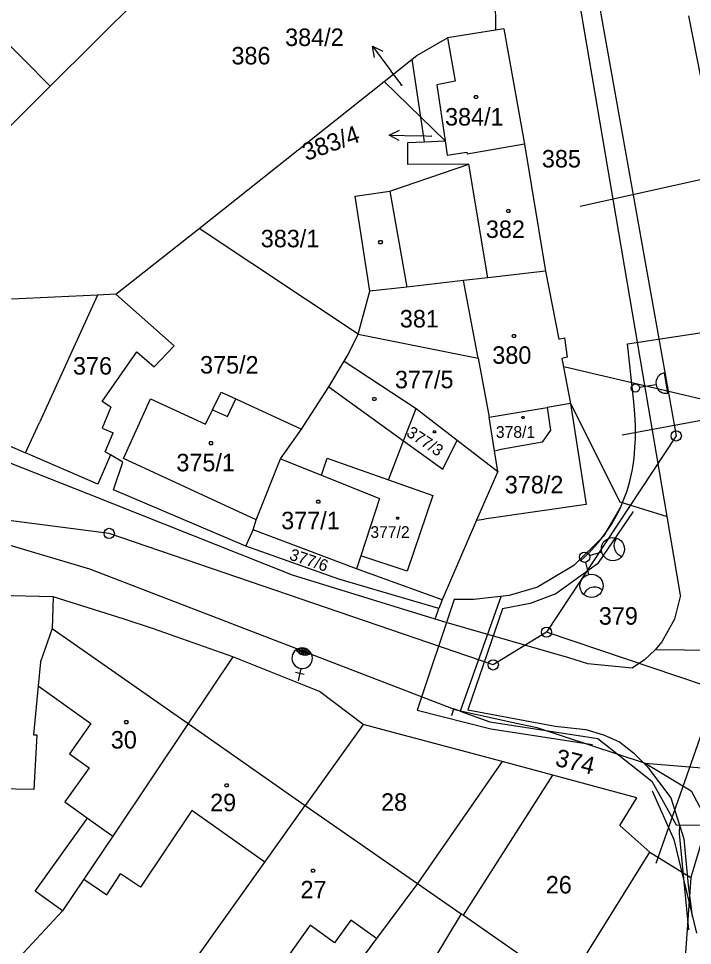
# Model space of a CAD drawing. Extents: x -639621 to -639329, y -1192893 to -1192488.
# Drawn here: x -639562.8 to -639497.3, y -1192743.8 to -1192653.7 of the extents above; entities that cross this region are included whole.
import ezdxf

# ---------------------------------------------------------------- set-up
doc = ezdxf.new("R2010")
doc.units = 0
for name, color, linetype in [('Vrstva 1', 7, 'Continuous'), ('Vrstva 19', 7, 'Continuous'), ('Vrstva 2', 7, 'Continuous'), ('Vrstva 20', 7, 'Continuous'), ('Vrstva 21', 7, 'Continuous'), ('Vrstva 22', 7, 'Continuous'), ('Vrstva 24', 7, 'Continuous'), ('Vrstva 25', 7, 'Continuous'), ('Vrstva 4', 7, 'Continuous'), ('Vrstva 5', 7, 'Continuous'), ('Vrstva 7', 7, 'Continuous')]:
    doc.layers.add(name, color=color, linetype=linetype)

msp = doc.modelspace()

# ---------------------------------------------------------------- linework, layer by layer
at = {"layer": 'Vrstva 1'}
for p, q in [((-639516.92, -1192617.59), (-639516.39, -1192654.83)), ((-639499.71, -1192702.08), (-639511.27, -1192634.08)), ((-639559.67, -1192660.27), (-639546.32, -1192646.99)), ((-639568.41, -1192651.47), (-639559.67, -1192660.27)), ((-639490.92, -1192687.58), (-639497.61, -1192653.45)), ((-639516.39, -1192654.83), (-639521.06, -1192655.58)), ((-639515.58, -1192654.7), (-639516.39, -1192654.83)), ((-639515.58, -1192654.7), (-639513.58, -1192665.9)), ((-639524.03, -1192657.28), (-639521.06, -1192655.58)), ((-639527.23, -1192659.81), (-639524.51, -1192657.66)), ((-639524.51, -1192657.66), (-639524.03, -1192657.28)), ((-639523.66, -1192663.29), (-639524.51, -1192657.66)), ((-639573.4, -1192673.94), (-639559.67, -1192660.27)), ((-639545.2, -1192674.09), (-639527.23, -1192659.81)), ((-639523.66, -1192663.29), (-639527.23, -1192659.81)), ((-639523.66, -1192663.29), (-639521.3, -1192665.59)), ((-639523.3, -1192665.67), (-639523.66, -1192663.29)), ((-639524.92, -1192665.73), (-639523.3, -1192665.67)), ((-639524.91, -1192667.89), (-639524.92, -1192665.73)), ((-639523.3, -1192665.67), (-639521.3, -1192665.59)), ((-639521.3, -1192665.59), (-639521.09, -1192666.98)), ((-639513.58, -1192665.9), (-639519.15, -1192666.89)), ((-639513.58, -1192665.9), (-639511.54, -1192678.25)), ((-639521.09, -1192666.98), (-639519.18, -1192666.7)), ((-639519.18, -1192666.7), (-639519.15, -1192666.89)), ((-639526.67, -1192670.46), (-639518.99, -1192667.84)), ((-639518.99, -1192667.84), (-639524.91, -1192667.89)), ((-639530.04, -1192670.97), (-639526.67, -1192670.46)), ((-639528.62, -1192680.2), (-639530.04, -1192670.97)), ((-639553.28, -1192680.5), (-639545.2, -1192674.09)), ((-639529.75, -1192684.37), (-639545.2, -1192674.09)), ((-639511.54, -1192678.25), (-639517.13, -1192678.89)), ((-639511.54, -1192678.25), (-639510.25, -1192684.87)), ((-639519.5, -1192679.16), (-639525, -1192679.79)), ((-639517.13, -1192678.89), (-639519.5, -1192679.16)), ((-639518.08, -1192686.72), (-639519.5, -1192679.16)), ((-639529.75, -1192684.37), (-639528.62, -1192680.2)), ((-639525, -1192679.79), (-639528.62, -1192680.2)), ((-639555.06, -1192680.58), (-639563.42, -1192680.98)), ((-639555.06, -1192680.58), (-639560.72, -1192692.94)), ((-639553.28, -1192680.5), (-639555.06, -1192680.58)), ((-639547.62, -1192685.52), (-639553.28, -1192680.5)), ((-639530.73, -1192686.34), (-639529.75, -1192684.37)), ((-639529.75, -1192684.37), (-639518.08, -1192686.72)), ((-639510.25, -1192684.87), (-639509.7, -1192684.74)), ((-639509.7, -1192684.74), (-639509.43, -1192686.62)), ((-639549.57, -1192687.53), (-639547.62, -1192685.52)), ((-639554.62, -1192690.9), (-639551.25, -1192686.09)), ((-639551.25, -1192686.09), (-639549.57, -1192687.53)), ((-639531.11, -1192686.99), (-639530.73, -1192686.34)), ((-639509.43, -1192686.62), (-639509.96, -1192686.74)), ((-639532.58, -1192689.5), (-639531.11, -1192686.99)), ((-639531.11, -1192686.99), (-639524.12, -1192691.61)), ((-639518.08, -1192686.72), (-639517.01, -1192692.43)), ((-639509.96, -1192686.74), (-639509.12, -1192691.12)), ((-639543.9, -1192691.72), (-639543.06, -1192690)), ((-639543.06, -1192690), (-639541.63, -1192690.66)), ((-639535.25, -1192693.61), (-639532.58, -1192689.5)), ((-639553.78, -1192691.45), (-639554.62, -1192690.9)), ((-639552.55, -1192696.45), (-639549.92, -1192690.66)), ((-639549.92, -1192690.66), (-639544.58, -1192693.13)), ((-639541.63, -1192690.66), (-639535.25, -1192693.61)), ((-639509.12, -1192691.12), (-639511.39, -1192691.5)), ((-639509.12, -1192691.12), (-639504.3, -1192700.68)), ((-639509.12, -1192691.12), (-639507.59, -1192700.94)), ((-639553.78, -1192691.45), (-639554.63, -1192693.5)), ((-639544.58, -1192693.13), (-639543.9, -1192691.72)), ((-639525.33, -1192694.73), (-639524.12, -1192691.61)), ((-639524.12, -1192691.61), (-639520.13, -1192694.67)), ((-639517.01, -1192692.43), (-639511.39, -1192691.5)), ((-639511.39, -1192691.5), (-639511.04, -1192693.7)), ((-639562.08, -1192695.91), (-639560.72, -1192692.94)), ((-639516.49, -1192695.7), (-639517.01, -1192692.43)), ((-639554.63, -1192693.5), (-639553.55, -1192693.95)), ((-639537.29, -1192696.49), (-639535.25, -1192693.61)), ((-639511.04, -1192693.7), (-639511.86, -1192694.86)), ((-639564.69, -1192694.76), (-639562.08, -1192695.91)), ((-639554.32, -1192695.81), (-639553.55, -1192693.95)), ((-639526.8, -1192698.52), (-639525.33, -1192694.73)), ((-639520.13, -1192694.67), (-639516.17, -1192697.71)), ((-639516.49, -1192695.7), (-639516.03, -1192695.62)), ((-639511.86, -1192694.86), (-639516.03, -1192695.62)), ((-639556.03, -1192699.88), (-639564.99, -1192696.36)), ((-639555.03, -1192698.94), (-639562.08, -1192695.91)), ((-639553.81, -1192696.1), (-639555.03, -1192698.94)), ((-639553.81, -1192696.1), (-639554.32, -1192695.81)), ((-639552.6, -1192696.8), (-639553.81, -1192696.1)), ((-639539.66, -1192702.42), (-639552.55, -1192696.45)), ((-639539.66, -1192702.42), (-639537.29, -1192696.49)), ((-639533.3, -1192698.08), (-639532.75, -1192696.42)), ((-639532.75, -1192696.42), (-639526.8, -1192698.52)), ((-639516.17, -1192697.71), (-639516.49, -1192695.7)), ((-639553.52, -1192699.51), (-639552.6, -1192696.8)), ((-639533.3, -1192698.08), (-639527.66, -1192700.33)), ((-639516.17, -1192697.71), (-639518.23, -1192702.46)), ((-639526.8, -1192698.52), (-639522.5, -1192700.06)), ((-639536.13, -1192707.8), (-639556.03, -1192699.88)), ((-639540.65, -1192704.97), (-639553.52, -1192699.51)), ((-639522.5, -1192700.06), (-639524.99, -1192707.41)), ((-639527.66, -1192700.33), (-639529.47, -1192705.92)), ((-639507.59, -1192700.94), (-639517.51, -1192702.36)), ((-639504.3, -1192700.68), (-639499.71, -1192702.08)), ((-639539.95, -1192703.37), (-639539.66, -1192702.42)), ((-639518.23, -1192702.46), (-639521.59, -1192710.19)), ((-639518.23, -1192702.46), (-639517.51, -1192702.36)), ((-639498.41, -1192709.74), (-639499.71, -1192702.08)), ((-639567.36, -1192703.76), (-639555.84, -1192707.16)), ((-639540.65, -1192704.97), (-639539.95, -1192703.37)), ((-639529.9, -1192707.18), (-639539.95, -1192703.37)), ((-639531.62, -1192708.19), (-639540.65, -1192704.97)), ((-639529.47, -1192705.92), (-639529.9, -1192707.18)), ((-639524.99, -1192707.41), (-639529.47, -1192705.92)), ((-639555.84, -1192707.16), (-639520.25, -1192720.87)), ((-639521.59, -1192710.19), (-639529.9, -1192707.18)), ((-639522.25, -1192712.07), (-639536.13, -1192707.8)), ((-639521.89, -1192711.04), (-639531.62, -1192708.19)), ((-639559.39, -1192709.9), (-639575.47, -1192709.49)), ((-639559.39, -1192709.9), (-639559.48, -1192712.99)), ((-639552.59, -1192712.04), (-639559.39, -1192709.9)), ((-639498.41, -1192709.74), (-639499.01, -1192712.06)), ((-639521.59, -1192710.19), (-639521.89, -1192711.04)), ((-639522.25, -1192712.07), (-639521.89, -1192711.04)), ((-639549.63, -1192713), (-639552.59, -1192712.04)), ((-639521.18, -1192712.4), (-639522.25, -1192712.07)), ((-639509.27, -1192715.82), (-639521.18, -1192712.4)), ((-639499.01, -1192712.06), (-639500.24, -1192714.27)), ((-639559.48, -1192712.99), (-639560.6, -1192716.22)), ((-639541.91, -1192715.74), (-639549.63, -1192713)), ((-639500.24, -1192714.27), (-639500.89, -1192715.05)), ((-639500.89, -1192715.05), (-639501.93, -1192716.01)), ((-639485.5, -1192715.26), (-639500.89, -1192715.05)), ((-639560.6, -1192716.22), (-639560.83, -1192718.54)), ((-639541.91, -1192715.74), (-639546.26, -1192722.22)), ((-639533.5, -1192719.11), (-639541.91, -1192715.74)), ((-639507.41, -1192716.4), (-639509.27, -1192715.82)), ((-639503.12, -1192716.84), (-639507.41, -1192716.4)), ((-639501.93, -1192716.01), (-639503.12, -1192716.84)), ((-639560.83, -1192718.54), (-639561.29, -1192723.32)), ((-639560.83, -1192718.54), (-639555.71, -1192722.22)), ((-639529.26, -1192722.31), (-639533.5, -1192719.11)), ((-639520.25, -1192720.87), (-639514.8, -1192722.07)), ((-639555.71, -1192722.22), (-639557.8, -1192725.14)), ((-639546.26, -1192722.22), (-639553.6, -1192733.16)), ((-639529.26, -1192722.31), (-639534.88, -1192730.18)), ((-639515.75, -1192725.9), (-639529.26, -1192722.31)), ((-639514.8, -1192722.07), (-639512.37, -1192722.6)), ((-639512.37, -1192722.6), (-639501.84, -1192726.06)), ((-639561.29, -1192723.32), (-639560.98, -1192723.31)), ((-639560.98, -1192723.31), (-639561.27, -1192728.63)), ((-639557.8, -1192725.14), (-639555.88, -1192726.52)), ((-639515.75, -1192725.9), (-639523.97, -1192737.75)), ((-639510.81, -1192727.24), (-639515.75, -1192725.9)), ((-639501.84, -1192726.06), (-639484.21, -1192727.56)), ((-639501.84, -1192726.06), (-639497.38, -1192728.76)), ((-639555.88, -1192726.52), (-639558.25, -1192729.81)), ((-639519.51, -1192740.84), (-639510.81, -1192727.24)), ((-639502.67, -1192729.44), (-639510.81, -1192727.24)), ((-639561.27, -1192728.63), (-639565.56, -1192728.52)), ((-639497.38, -1192728.76), (-639495.79, -1192731.74)), ((-639558.25, -1192729.81), (-639556.04, -1192731.4)), ((-639504.3, -1192732.11), (-639502.67, -1192729.44)), ((-639538.8, -1192735.67), (-639534.88, -1192730.18)), ((-639534.88, -1192730.18), (-639523.97, -1192737.75)), ((-639561.14, -1192738.49), (-639556.04, -1192731.4)), ((-639501.41, -1192734.7), (-639504.3, -1192732.11)), ((-639495.79, -1192731.74), (-639497.4, -1192737.18)), ((-639553.6, -1192733.16), (-639556.41, -1192737.34)), ((-639509.52, -1192747.76), (-639501.41, -1192734.7)), ((-639501.41, -1192734.7), (-639497.4, -1192737.18)), ((-639551.56, -1192753.52), (-639538.8, -1192735.67)), ((-639556.41, -1192737.34), (-639558.48, -1192740.42)), ((-639523.97, -1192737.75), (-639527.96, -1192743.09)), ((-639497.4, -1192737.18), (-639499.22, -1192762.27)), ((-639558.48, -1192740.42), (-639561.14, -1192738.49)), ((-639558.48, -1192740.42), (-639567.88, -1192750.5)), ((-639519.72, -1192740.7), (-639522.79, -1192745.74)), ((-639519.72, -1192740.7), (-639519.51, -1192740.84)), ((-639519.51, -1192740.84), (-639509.52, -1192747.76)), ((-639527.96, -1192743.09), (-639541.39, -1192761.03))]:
    msp.add_line(p, q, dxfattribs=at)
at = {"layer": 'Vrstva 19'}
for points in [[(-639583.962, -1192528.01), (-639550.452, -1192564.184), (-639529.583, -1192588.026), (-639514.491, -1192612.048), (-639507.737, -1192644.326), (-639498.832, -1192694.254), (-639511.439, -1192713.331), (-639516.613, -1192716.507), (-639553.938, -1192703.739), (-639570.485, -1192701.616), (-639578.687, -1192703.18)], [(-639355.755, -1192712.633), (-639405.298, -1192719.503), (-639444.905, -1192722.803), (-639490.998, -1192720.223), (-639511.439, -1192713.331)]]:
    msp.add_lwpolyline(points, dxfattribs=at)
for centre in [(-639498.832, -1192694.254), (-639553.938, -1192703.739), (-639511.439, -1192713.331), (-639516.613, -1192716.507)]:
    msp.add_circle(centre, 0.5, dxfattribs=at)
at = {"layer": 'Vrstva 20'}
for points in [[(-639509.769, -1192687.519), (-639485.819, -1192693.156)], [(-639500.783, -1192735.773), (-639485.819, -1192693.156)]]:
    msp.add_lwpolyline(points, dxfattribs=at)
at = {"layer": 'Vrstva 21'}
msp.add_lwpolyline([(-639504.241, -1192701.192), (-639505.905, -1192703.987), (-639508.782, -1192706.864), (-639512.31, -1192708.965), (-639515.077, -1192709.767), (-639518.505, -1192710.144), (-639520.398, -1192710.144), (-639524.02, -1192720.907), (-639516.84, -1192722.729), (-639509.886, -1192723.806), (-639506.984, -1192724.251)], dxfattribs=at)
at = {"layer": 'Vrstva 22'}
for p, q in [((-639502.402, -1192689.51), (-639500.799, -1192689.247)), ((-639507.267, -1192705.866), (-639506.075, -1192705.531)), ((-639507.66, -1192706.539), (-639507.366, -1192707.742)), ((-639535.778, -1192715.073), (-639534.348, -1192715.371)), ((-639535.662, -1192715.212), (-639535.613, -1192714.974)), ((-639534.489, -1192715.453), (-639535.643, -1192715.216)), ((-639535.613, -1192714.974), (-639534.441, -1192715.216)), ((-639535.409, -1192714.892), (-639535.504, -1192715.349)), ((-639535.504, -1192715.349), (-639534.66, -1192715.523)), ((-639534.567, -1192715.076), (-639535.409, -1192714.892)), ((-639535.199, -1192714.874), (-639535.297, -1192715.453)), ((-639535.297, -1192715.453), (-639534.855, -1192715.565)), ((-639534.734, -1192714.981), (-639535.18, -1192714.886)), ((-639534.98, -1192714.918), (-639535.105, -1192715.524)), ((-639534.855, -1192715.565), (-639534.734, -1192714.981)), ((-639534.66, -1192715.523), (-639534.567, -1192715.076)), ((-639534.441, -1192715.216), (-639534.489, -1192715.453)), ((-639535.831, -1192717.215), (-639535.001, -1192717.396)), ((-639535.3, -1192716.856), (-639535.56, -1192718.049))]:
    msp.add_line(p, q, dxfattribs=at)
for points in [[(-639503.007, -1192690.368), (-639503.57, -1192685.327), (-639487.98, -1192682.937)], [(-639499.645, -1192690.103), (-639499.969, -1192688.128)], [(-639508.109, -1192706.375), (-639507.734, -1192706.044), (-639507.157, -1192705.475), (-639506.662, -1192704.935), (-639506.183, -1192704.36), (-639505.628, -1192703.614), (-639505.097, -1192702.802), (-639504.638, -1192701.997), (-639504.261, -1192701.237), (-639503.907, -1192700.41), (-639503.612, -1192699.594), (-639503.33, -1192698.641), (-639503.082, -1192697.518), (-639502.921, -1192696.417), (-639502.841, -1192695.404), (-639502.805, -1192694.473), (-639502.803, -1192693.26), (-639502.846, -1192692.155), (-639502.942, -1192690.954), (-639503.007, -1192690.373)]]:
    msp.add_lwpolyline(points, dxfattribs=at)
for centre, radius in [((-639502.796, -1192689.602), 0.4), ((-639504.983, -1192705.259), 1.125), ((-639507.734, -1192706.044), 0.5), ((-639507.065, -1192708.826), 1.125)]:
    msp.add_circle(centre, radius, dxfattribs=at)
for centre, radius, start, end in [((-639499.807, -1192689.116), 1.001, 99.30226, 189.30226), ((-639499.807, -1192689.116), 1.001, 189.30226, 279.30226), ((-639503.755, -1192704.904), 1.125, 140.76439, 251.47672), ((-639506.771, -1192710.07), 1.125, 47.9657, 158.67804), ((-639535.182, -1192715.862), 1, 125.42147, 124.57372), ((-639534.909, -1192714.542), 1, 210.62549, 306.53322)]:
    msp.add_arc(centre, radius, start, end, dxfattribs=at)
at = {"layer": 'Vrstva 24'}
for p, q in [((-639520.47, -1192720.793), (-639520.657, -1192721.474)), ((-639519.839, -1192721.018), (-639520.47, -1192720.793)), ((-639498.498, -1192732.895), (-639498.489, -1192732.056)), ((-639497.601, -1192742.26), (-639498.498, -1192732.895))]:
    msp.add_line(p, q, dxfattribs=at)
msp.add_lwpolyline([(-639515.87, -1192709.897), (-639519.839, -1192721.018), (-639516.938, -1192722.054), (-639506.439, -1192723.649), (-639501.216, -1192727.825), (-639498.838, -1192732.052), (-639488.74, -1192732.165), (-639484.493, -1192728.011), (-639466.499, -1192728.212)], dxfattribs=at)
at = {"layer": 'Vrstva 25'}
for p, q in [((-639493.98, -1192668.81), (-639508.152, -1192671.961)), ((-639501.158, -1192728.756), (-639499.048, -1192733.476)), ((-639499.048, -1192733.476), (-639496.86, -1192742.59))]:
    msp.add_line(p, q, dxfattribs=at)
for points in [[(-639460.277, -1192719.081), (-639470.702, -1192714.682), (-639477.01, -1192709.489), (-639481.198, -1192702.482), (-639485.834, -1192697.846), (-639487.986, -1192691.193), (-639504.096, -1192694.186)], [(-639503.001, -1192701.594), (-639506.486, -1192706.69), (-639510.516, -1192709.592), (-639513.013, -1192710.551), (-639515.716, -1192711.06), (-639519.07, -1192720.886), (-639510.612, -1192722.45), (-639507.627, -1192722.785), (-639505.909, -1192723.303), (-639504.328, -1192723.976), (-639502.972, -1192725.053), (-639501.648, -1192726.377), (-639499.349, -1192729.422), (-639498.089, -1192733.403), (-639497.666, -1192737.93), (-639497.276, -1192740.949)]]:
    msp.add_lwpolyline(points, dxfattribs=at)
at = {"layer": 'Vrstva 4'}
for p, q in [((-639521.06, -1192655.58), (-639520.33, -1192659.8)), ((-639520.33, -1192659.8), (-639522.11, -1192660.14)), ((-639522.11, -1192660.14), (-639521.3, -1192665.59)), ((-639517.13, -1192678.89), (-639518.99, -1192667.84)), ((-639526.67, -1192670.46), (-639525, -1192679.79)), ((-639532.58, -1192689.5), (-639525.33, -1192694.73)), ((-639542.44, -1192692.36), (-639541.63, -1192690.66)), ((-639543.9, -1192691.72), (-639542.44, -1192692.36)), ((-639525.33, -1192694.73), (-639521.51, -1192697.49)), ((-639521.51, -1192697.49), (-639520.13, -1192694.67)), ((-639537.29, -1192696.49), (-639533.3, -1192698.08)), ((-639559.48, -1192712.99), (-639546.26, -1192722.22)), ((-639546.26, -1192722.22), (-639534.88, -1192730.18)), ((-639545.9, -1192730.65), (-639550.91, -1192738.12)), ((-639538.8, -1192735.67), (-639545.9, -1192730.65)), ((-639556.04, -1192731.4), (-639553.6, -1192733.16)), ((-639554.18, -1192738.84), (-639552.83, -1192736.83)), ((-639550.91, -1192738.12), (-639552.83, -1192736.83)), ((-639556.41, -1192737.34), (-639554.18, -1192738.84)), ((-639523.97, -1192737.75), (-639519.72, -1192740.7)), ((-639530.45, -1192741.31), (-639532.03, -1192743.51)), ((-639527.96, -1192743.09), (-639530.45, -1192741.31)), ((-639534.41, -1192741.81), (-639537.06, -1192745.52)), ((-639532.03, -1192743.51), (-639534.41, -1192741.81))]:
    msp.add_line(p, q, dxfattribs=at)
at = {"layer": 'Vrstva 5'}
for points in [[(-639518.19, -1192661.18), (-639518.1, -1192661.33), (-639518.19, -1192661.48), (-639518.37, -1192661.48), (-639518.46, -1192661.33), (-639518.37, -1192661.18)], [(-639515.07, -1192672.25), (-639514.98, -1192672.4), (-639515.07, -1192672.55), (-639515.25, -1192672.55), (-639515.34, -1192672.4), (-639515.25, -1192672.25)], [(-639527.48, -1192675.28), (-639527.39, -1192675.43), (-639527.48, -1192675.58), (-639527.66, -1192675.58), (-639527.75, -1192675.43), (-639527.66, -1192675.28)], [(-639514.52, -1192684.4), (-639514.43, -1192684.55), (-639514.52, -1192684.7), (-639514.7, -1192684.7), (-639514.79, -1192684.55), (-639514.7, -1192684.4)], [(-639528.07, -1192690.52), (-639527.98, -1192690.67), (-639528.07, -1192690.82), (-639528.25, -1192690.82), (-639528.34, -1192690.67), (-639528.25, -1192690.52)], [(-639513.67, -1192692.38), (-639513.609, -1192692.48), (-639513.67, -1192692.58), (-639513.79, -1192692.58), (-639513.851, -1192692.48), (-639513.79, -1192692.38)], [(-639522.27, -1192693.75), (-639522.209, -1192693.85), (-639522.27, -1192693.95), (-639522.39, -1192693.95), (-639522.451, -1192693.85), (-639522.39, -1192693.75)], [(-639543.96, -1192694.81), (-639543.87, -1192694.96), (-639543.96, -1192695.11), (-639544.14, -1192695.11), (-639544.23, -1192694.96), (-639544.14, -1192694.81)], [(-639533.53, -1192700.51), (-639533.44, -1192700.66), (-639533.53, -1192700.81), (-639533.71, -1192700.81), (-639533.8, -1192700.66), (-639533.71, -1192700.51)], [(-639525.84, -1192702.15), (-639525.779, -1192702.25), (-639525.84, -1192702.35), (-639525.96, -1192702.35), (-639526.021, -1192702.25), (-639525.96, -1192702.15)], [(-639552.19, -1192721.93), (-639552.1, -1192722.08), (-639552.19, -1192722.23), (-639552.37, -1192722.23), (-639552.46, -1192722.08), (-639552.37, -1192721.93)], [(-639542.44, -1192728.07), (-639542.35, -1192728.22), (-639542.44, -1192728.37), (-639542.62, -1192728.37), (-639542.71, -1192728.22), (-639542.62, -1192728.07)], [(-639534.03, -1192736.35), (-639533.94, -1192736.5), (-639534.03, -1192736.65), (-639534.21, -1192736.65), (-639534.3, -1192736.5), (-639534.21, -1192736.35)]]:
    msp.add_lwpolyline(points, close=True, dxfattribs=at)
at = {"layer": 'Vrstva 7'}
for p, q in [((-639528.361, -1192656.371), (-639526.56, -1192658.77)), ((-639525.47, -1192660.22), (-639526.56, -1192658.77)), ((-639526.729, -1192665.018), (-639523.73, -1192665.11)), ((-639522.57, -1192665.15), (-639523.73, -1192665.11))]:
    msp.add_line(p, q, dxfattribs=at)
for points in [[(-639528.161, -1192657.471), (-639528.361, -1192656.371), (-639527.361, -1192656.87)], [(-639525.744, -1192665.548), (-639526.729, -1192665.018), (-639525.714, -1192664.549)]]:
    msp.add_lwpolyline(points, dxfattribs=at)

# ---------------------------------------------------------------- texts
at = {"layer": 'Vrstva 2'}
for s, height, p in [('386', 1.7, (-639542.058, -1192658.16)), ('384/2', 0.1, (-639525.683, -1192660.22)), ('384/1', 1.7, (-639521.299, -1192664.1)), ('383/4', 0.1, (-639522.784, -1192665.15)), ('385', 1.7, (-639511.886, -1192668.174)), ('382', 1.7, (-639517.332, -1192675.02)), ('383/1', 1.7, (-639539.206, -1192675.93)), ('381', 1.7, (-639525.69, -1192683.72)), ('380', 1.7, (-639516.705, -1192687.25)), ('376', 1.7, (-639557.461, -1192688.3)), ('375/2', 1.7, (-639545.111, -1192688.2)), ('377/5', 1.7, (-639526.167, -1192689.63)), ('378/1', 1.14, (-639516.358, -1192694.45)), ('375/1', 1.7, (-639547.409, -1192697.7)), ('378/2', 1.7, (-639515.49, -1192699.84)), ('377/1', 1.7, (-639537.222, -1192703.33)), ('377/2', 1.14, (-639528.556, -1192704.17)), ('379', 1.7, (-639506.352, -1192712.601)), ('30', 1.7, (-639553.779, -1192724.64)), ('29', 1.7, (-639544.129, -1192730.73)), ('28', 1.7, (-639527.519, -1192730.69)), ('26', 1.7, (-639511.509, -1192738.72)), ('27', 1.7, (-639535.348, -1192739.2))]:
    msp.add_text(s, height=height, dxfattribs=at).set_placement(p)
for s, height, rotation, p in [('377/3', 1.14, 326.41406, (-639525.14, -1192694.192)), ('377/6', 1.14, 341.42555, (-639536.507, -1192706.255)), ('374', 1.7, 346.20913, (-639510.682, -1192726.291))]:
    msp.add_text(s, height=height, rotation=rotation, dxfattribs=at).set_placement(p)
at = {"layer": 'Vrstva 7'}
msp.add_text('384/2', height=1.7, dxfattribs=at).set_placement((-639536.839, -1192656.37))
msp.add_text('383/4', height=1.7, rotation=19.76704, dxfattribs=at).set_placement((-639534.794, -1192667.558))

doc.saveas('drawing.dxf')
